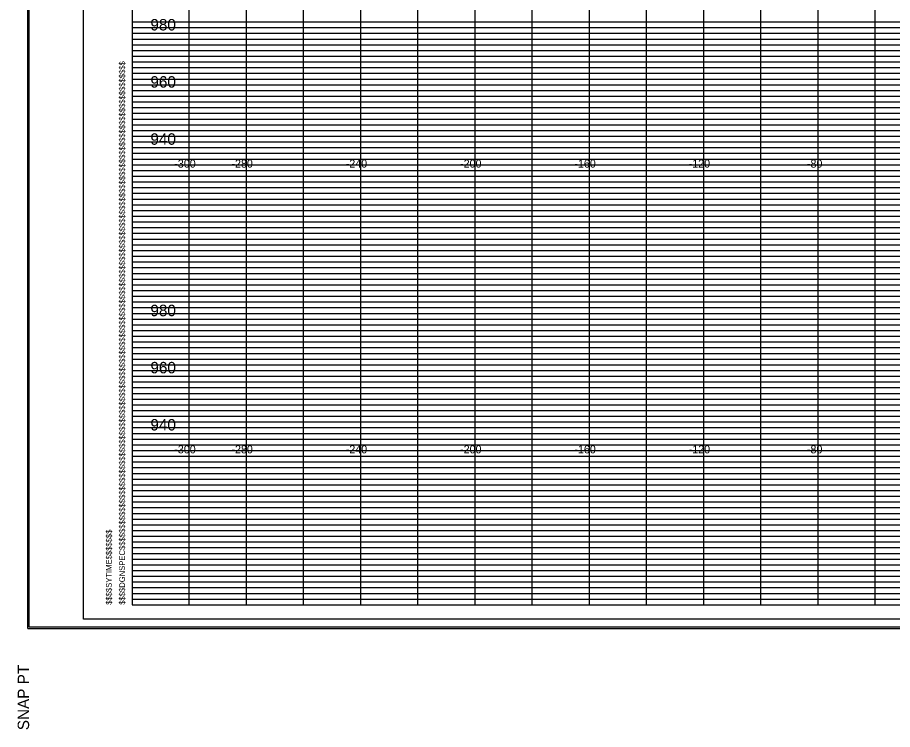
# Model space of a CAD drawing. Extents: x 2313580 to 2322968, y 282099 to 303247.
# Drawn here: x 2319214.8 to 2319520.9, y 287544 to 287793.2 of the extents above; entities that cross this region are included whole.
import ezdxf

# ---------------------------------------------------------------- set-up
doc = ezdxf.new("R2010")
doc.units = 0
for name, color, linetype in [('DESIGN - SHEET - Corner Text', 7, 'Continuous'), ('DESIGN - SHEET - Light Grid', 7, 'Continuous'), ('DESIGN - SHEET - Linework', 7, 'Continuous'), ('DESIGN - SHEET - Plot Shape', 7, 'Continuous'), ('DESIGN - TYPICAL - Text', 7, 'Continuous')]:
    doc.layers.add(name, color=color, linetype=linetype)

msp = doc.modelspace()

# ---------------------------------------------------------------- linework, layer by layer
at = {"layer": 'DESIGN - SHEET - Light Grid'}
for p, q in [((2319254.88, 287791.67), (2319414.88, 287791.67)), ((2319254.88, 287789.67), (2319414.88, 287789.67)), ((2319414.88, 287791.67), (2319574.88, 287791.67)), ((2319414.88, 287789.67), (2319574.88, 287789.67)), ((2319254.88, 287785.67), (2319414.88, 287785.67)), ((2319414.88, 287785.67), (2319574.88, 287785.67)), ((2319254.88, 287783.67), (2319414.88, 287783.67)), ((2319414.88, 287783.67), (2319574.88, 287783.67)), ((2319254.88, 287781.67), (2319414.88, 287781.67)), ((2319254.88, 287779.67), (2319414.88, 287779.67)), ((2319414.88, 287781.67), (2319574.88, 287781.67)), ((2319414.88, 287779.67), (2319574.88, 287779.67)), ((2319254.88, 287777.67), (2319414.88, 287777.67)), ((2319414.88, 287777.67), (2319574.88, 287777.67)), ((2319254.88, 287775.67), (2319414.88, 287775.67)), ((2319254.88, 287773.67), (2319414.88, 287773.67)), ((2319414.88, 287775.67), (2319574.88, 287775.67)), ((2319414.88, 287773.67), (2319574.88, 287773.67)), ((2319254.88, 287771.67), (2319414.88, 287771.67)), ((2319414.88, 287771.67), (2319574.88, 287771.67)), ((2319254.88, 287769.67), (2319414.88, 287769.67)), ((2319414.88, 287769.67), (2319574.88, 287769.67)), ((2319254.88, 287765.67), (2319414.88, 287765.67)), ((2319414.88, 287765.67), (2319574.88, 287765.67)), ((2319254.88, 287763.67), (2319414.88, 287763.67)), ((2319254.88, 287761.67), (2319414.88, 287761.67)), ((2319414.88, 287763.67), (2319574.88, 287763.67)), ((2319414.88, 287761.67), (2319574.88, 287761.67)), ((2319254.88, 287759.67), (2319414.88, 287759.67)), ((2319414.88, 287759.67), (2319574.88, 287759.67)), ((2319254.88, 287757.67), (2319414.88, 287757.67)), ((2319254.88, 287755.67), (2319414.88, 287755.67)), ((2319414.88, 287757.67), (2319574.88, 287757.67)), ((2319414.88, 287755.67), (2319574.88, 287755.67)), ((2319254.88, 287753.67), (2319414.88, 287753.67)), ((2319414.88, 287753.67), (2319574.88, 287753.67)), ((2319254.88, 287751.67), (2319414.88, 287751.67)), ((2319254.88, 287749.67), (2319414.88, 287749.67)), ((2319414.88, 287751.67), (2319574.88, 287751.67)), ((2319414.88, 287749.67), (2319574.88, 287749.67)), ((2319254.88, 287745.67), (2319414.88, 287745.67)), ((2319254.88, 287743.67), (2319414.88, 287743.67)), ((2319414.88, 287745.67), (2319574.88, 287745.67)), ((2319414.88, 287743.67), (2319574.88, 287743.67)), ((2319254.88, 287741.67), (2319414.88, 287741.67)), ((2319414.88, 287741.67), (2319574.88, 287741.67)), ((2319254.88, 287739.67), (2319414.88, 287739.67)), ((2319254.88, 287737.67), (2319414.88, 287737.67)), ((2319414.88, 287739.67), (2319574.88, 287739.67)), ((2319414.88, 287737.67), (2319574.88, 287737.67)), ((2319254.88, 287735.67), (2319414.88, 287735.67)), ((2319254.88, 287733.67), (2319414.88, 287733.67)), ((2319414.88, 287735.67), (2319574.88, 287735.67)), ((2319414.88, 287733.67), (2319574.88, 287733.67)), ((2319254.88, 287731.67), (2319414.88, 287731.67)), ((2319414.88, 287731.67), (2319574.88, 287731.67)), ((2319254.88, 287729.67), (2319414.88, 287729.67)), ((2319414.88, 287729.67), (2319574.88, 287729.67)), ((2319254.88, 287725.67), (2319414.88, 287725.67)), ((2319414.88, 287725.67), (2319574.88, 287725.67)), ((2319254.88, 287723.67), (2319414.88, 287723.67)), ((2319254.88, 287721.67), (2319414.88, 287721.67)), ((2319414.88, 287723.67), (2319574.88, 287723.67)), ((2319414.88, 287721.67), (2319574.88, 287721.67)), ((2319254.88, 287719.67), (2319414.88, 287719.67)), ((2319414.88, 287719.67), (2319574.88, 287719.67)), ((2319254.88, 287717.67), (2319414.88, 287717.67)), ((2319254.88, 287715.67), (2319414.88, 287715.67)), ((2319414.88, 287717.67), (2319574.88, 287717.67)), ((2319414.88, 287715.67), (2319574.88, 287715.67)), ((2319254.88, 287713.67), (2319414.88, 287713.67)), ((2319414.88, 287713.67), (2319574.88, 287713.67)), ((2319254.88, 287711.67), (2319414.88, 287711.67)), ((2319254.88, 287709.67), (2319414.88, 287709.67)), ((2319414.88, 287711.67), (2319574.88, 287711.67)), ((2319414.88, 287709.67), (2319574.88, 287709.67)), ((2319254.88, 287705.67), (2319414.88, 287705.67)), ((2319254.88, 287703.67), (2319414.88, 287703.67)), ((2319414.88, 287705.67), (2319574.88, 287705.67)), ((2319414.88, 287703.67), (2319574.88, 287703.67)), ((2319254.88, 287701.67), (2319414.88, 287701.67)), ((2319414.88, 287701.67), (2319574.88, 287701.67)), ((2319254.88, 287699.67), (2319414.88, 287699.67)), ((2319254.88, 287697.67), (2319414.88, 287697.67)), ((2319414.88, 287699.67), (2319574.88, 287699.67)), ((2319414.88, 287697.67), (2319574.88, 287697.67)), ((2319254.88, 287695.67), (2319414.88, 287695.67)), ((2319414.88, 287695.67), (2319574.88, 287695.67)), ((2319254.88, 287693.67), (2319414.88, 287693.67)), ((2319254.88, 287691.67), (2319414.88, 287691.67)), ((2319414.88, 287693.67), (2319574.88, 287693.67)), ((2319414.88, 287691.67), (2319574.88, 287691.67)), ((2319254.88, 287689.67), (2319414.88, 287689.67)), ((2319414.88, 287689.67), (2319574.88, 287689.67)), ((2319254.88, 287685.67), (2319414.88, 287685.67)), ((2319414.88, 287685.67), (2319574.88, 287685.67)), ((2319254.88, 287683.67), (2319414.88, 287683.67)), ((2319254.88, 287681.67), (2319414.88, 287681.67)), ((2319414.88, 287683.67), (2319574.88, 287683.67)), ((2319414.88, 287681.67), (2319574.88, 287681.67)), ((2319254.88, 287679.67), (2319414.88, 287679.67)), ((2319414.88, 287679.67), (2319574.88, 287679.67)), ((2319254.88, 287677.67), (2319414.88, 287677.67)), ((2319254.88, 287675.67), (2319414.88, 287675.67)), ((2319414.88, 287677.67), (2319574.88, 287677.67)), ((2319414.88, 287675.67), (2319574.88, 287675.67)), ((2319254.88, 287673.67), (2319414.88, 287673.67)), ((2319414.88, 287673.67), (2319574.88, 287673.67)), ((2319254.88, 287671.67), (2319414.88, 287671.67)), ((2319254.88, 287669.67), (2319414.88, 287669.67)), ((2319414.88, 287671.67), (2319574.88, 287671.67)), ((2319414.88, 287669.67), (2319574.88, 287669.67)), ((2319254.88, 287665.67), (2319414.88, 287665.67)), ((2319254.88, 287663.67), (2319414.88, 287663.67)), ((2319414.88, 287665.67), (2319574.88, 287665.67)), ((2319414.88, 287663.67), (2319574.88, 287663.67)), ((2319254.88, 287661.67), (2319414.88, 287661.67)), ((2319414.88, 287661.67), (2319574.88, 287661.67)), ((2319254.88, 287659.67), (2319414.88, 287659.67)), ((2319254.88, 287657.67), (2319414.88, 287657.67)), ((2319414.88, 287659.67), (2319574.88, 287659.67)), ((2319414.88, 287657.67), (2319574.88, 287657.67)), ((2319254.88, 287655.67), (2319414.88, 287655.67)), ((2319414.88, 287655.67), (2319574.88, 287655.67)), ((2319254.88, 287653.67), (2319414.88, 287653.67)), ((2319254.88, 287651.67), (2319414.88, 287651.67)), ((2319414.88, 287653.67), (2319574.88, 287653.67)), ((2319414.88, 287651.67), (2319574.88, 287651.67)), ((2319254.88, 287649.67), (2319414.88, 287649.67)), ((2319414.88, 287649.67), (2319574.88, 287649.67)), ((2319254.88, 287645.67), (2319414.88, 287645.67)), ((2319414.88, 287645.67), (2319574.88, 287645.67)), ((2319254.88, 287643.67), (2319414.88, 287643.67)), ((2319414.88, 287643.67), (2319574.88, 287643.67)), ((2319254.88, 287641.67), (2319414.88, 287641.67)), ((2319254.88, 287639.67), (2319414.88, 287639.67)), ((2319414.88, 287641.67), (2319574.88, 287641.67)), ((2319414.88, 287639.67), (2319574.88, 287639.67)), ((2319254.88, 287637.67), (2319414.88, 287637.67)), ((2319254.88, 287635.67), (2319414.88, 287635.67)), ((2319414.88, 287637.67), (2319574.88, 287637.67)), ((2319414.88, 287635.67), (2319574.88, 287635.67)), ((2319254.88, 287633.67), (2319414.88, 287633.67)), ((2319414.88, 287633.67), (2319574.88, 287633.67)), ((2319254.88, 287631.67), (2319414.88, 287631.67)), ((2319254.88, 287629.67), (2319414.88, 287629.67)), ((2319414.88, 287631.67), (2319574.88, 287631.67)), ((2319414.88, 287629.67), (2319574.88, 287629.67)), ((2319254.88, 287625.67), (2319414.88, 287625.67)), ((2319254.88, 287623.67), (2319414.88, 287623.67)), ((2319414.88, 287625.67), (2319574.88, 287625.67)), ((2319414.88, 287623.67), (2319574.88, 287623.67)), ((2319254.88, 287621.67), (2319414.88, 287621.67)), ((2319414.88, 287621.67), (2319574.88, 287621.67)), ((2319254.88, 287619.67), (2319414.88, 287619.67)), ((2319254.88, 287617.67), (2319414.88, 287617.67)), ((2319414.88, 287619.67), (2319574.88, 287619.67)), ((2319414.88, 287617.67), (2319574.88, 287617.67)), ((2319254.88, 287615.67), (2319414.88, 287615.67)), ((2319414.88, 287615.67), (2319574.88, 287615.67)), ((2319254.88, 287613.67), (2319414.88, 287613.67)), ((2319254.88, 287611.67), (2319414.88, 287611.67)), ((2319414.88, 287613.67), (2319574.88, 287613.67)), ((2319414.88, 287611.67), (2319574.88, 287611.67)), ((2319254.88, 287609.67), (2319414.88, 287609.67)), ((2319414.88, 287609.67), (2319574.88, 287609.67)), ((2319254.88, 287605.67), (2319414.88, 287605.67)), ((2319414.88, 287605.67), (2319574.88, 287605.67)), ((2319254.88, 287603.67), (2319414.88, 287603.67)), ((2319414.88, 287603.67), (2319574.88, 287603.67)), ((2319254.88, 287601.67), (2319414.88, 287601.67)), ((2319254.88, 287599.67), (2319414.88, 287599.67)), ((2319414.88, 287601.67), (2319574.88, 287601.67)), ((2319414.88, 287599.67), (2319574.88, 287599.67)), ((2319254.88, 287597.67), (2319414.88, 287597.67)), ((2319414.88, 287597.67), (2319574.88, 287597.67)), ((2319254.88, 287595.67), (2319414.88, 287595.67)), ((2319254.88, 287593.67), (2319414.88, 287593.67)), ((2319414.88, 287595.67), (2319574.88, 287595.67)), ((2319414.88, 287593.67), (2319574.88, 287593.67)), ((2319254.88, 287591.67), (2319414.88, 287591.67)), ((2319414.88, 287591.67), (2319574.88, 287591.67)), ((2319254.88, 287589.67), (2319414.88, 287589.67)), ((2319414.88, 287589.67), (2319574.88, 287589.67))]:
    msp.add_line(p, q, dxfattribs=at)
at = {"layer": 'DESIGN - SHEET - Linework'}
for p, q in [((2319218.42, 287579.39), (2319218.42, 288015.95)), ((2319274.88, 287587.67), (2319274.88, 288007.67)), ((2319294.88, 287587.67), (2319294.88, 288007.67)), ((2319314.88, 287587.67), (2319314.88, 288007.67)), ((2319334.88, 287587.67), (2319334.88, 288007.67)), ((2319354.88, 287587.67), (2319354.88, 288007.67)), ((2319374.88, 287587.67), (2319374.88, 288007.67)), ((2319394.88, 287587.67), (2319394.88, 288007.67)), ((2319414.88, 287587.67), (2319414.88, 288007.67)), ((2319434.88, 287587.67), (2319434.88, 288007.67)), ((2319454.88, 287587.67), (2319454.88, 288007.67)), ((2319474.88, 287587.67), (2319474.88, 288007.67)), ((2319494.88, 287587.67), (2319494.88, 288007.67)), ((2319514.88, 287587.67), (2319514.88, 288007.67)), ((2319254.88, 287787.67), (2319894.88, 287787.67)), ((2319254.88, 287767.67), (2319894.88, 287767.67)), ((2319254.88, 287747.67), (2319894.88, 287747.67)), ((2319254.88, 287727.67), (2319894.88, 287727.67)), ((2319254.88, 287707.67), (2319894.88, 287707.67)), ((2319254.88, 287687.67), (2319894.88, 287687.67)), ((2319254.88, 287667.67), (2319894.88, 287667.67)), ((2319254.88, 287647.67), (2319894.88, 287647.67)), ((2319254.88, 287627.67), (2319894.88, 287627.67)), ((2319254.88, 287607.67), (2319894.88, 287607.67)), ((2319218.42, 287579.39), (2319899.22, 287579.39))]:
    msp.add_line(p, q, dxfattribs=at)
msp.add_lwpolyline([(2319254.88, 288007.67), (2319254.88, 287587.67), (2319894.88, 287587.67), (2319894.88, 288007.67), (2319254.88, 288007.67)], dxfattribs=at)
at = {"layer": 'DESIGN - SHEET - Plot Shape'}
for points in [[(2319218.82, 288015.55), (2319898.82, 288015.55), (2319898.82, 287579.79), (2319218.82, 287579.79)], [(2319237.88, 288007.67), (2319894.88, 288007.67), (2319894.88, 287582.67), (2319237.88, 287582.67)]]:
    msp.add_lwpolyline(points, close=True, dxfattribs=at)

# ---------------------------------------------------------------- texts
at = {"layer": 'DESIGN - SHEET - Corner Text'}
for s, height, p in [('$$$$DGNSPEC$$$$$$$$$$$$$$$$$$$$$$$$$$$$$$$$$$$$$$$$$$$$$$$$$$$$$$$$$$$$$$$$$$$$$$$$$$$$$$$$$$$$$$$$$$$$$$$$$$$$$$$$$$$$$$$$$$$', 2.00004, (2319252.36, 287587.67)), ('$$$$SYTIME$$$$$$$', 2, (2319247.72, 287587.67)), ('SNAP PT  ', 4, (2319218.82, 287543.79))]:
    msp.add_text(s, height=height, rotation=90, dxfattribs=at).set_placement(p)
at = {"layer": 'DESIGN - SHEET - Linework'}
for p in [(2319274.88, 287747.67), (2319274.88, 287647.67)]:
    msp.add_text('-', height=0.0001, dxfattribs=at).set_placement(p)
at = {"layer": 'DESIGN - TYPICAL - Text'}
for s, height, p in [('980', 4, (2319261.26, 287788.67)), ('960', 4, (2319261.26, 287768.67)), ('940', 4, (2319261.26, 287748.67)), ('-300', 2.8, (2319269.62, 287740.67)), ('-280', 2.8, (2319289.62, 287740.67)), ('-240', 2.8, (2319329.62, 287740.67)), ('-200', 2.8, (2319369.62, 287740.67)), ('-160', 2.8, (2319409.62, 287740.67)), ('-120', 2.8, (2319449.62, 287740.67)), ('-80', 2.8, (2319490.99, 287740.67)), ('980', 4, (2319261.26, 287688.67)), ('960', 4, (2319261.26, 287668.67)), ('940', 4, (2319261.26, 287648.67)), ('-300', 2.8, (2319269.62, 287640.67)), ('-280', 2.8, (2319289.62, 287640.67)), ('-240', 2.8, (2319329.62, 287640.67)), ('-200', 2.8, (2319369.62, 287640.67)), ('-160', 2.8, (2319409.62, 287640.67)), ('-120', 2.8, (2319449.62, 287640.67)), ('-80', 2.8, (2319490.99, 287640.67))]:
    msp.add_text(s, height=height, dxfattribs=at).set_placement(p)

doc.saveas('drawing.dxf')
